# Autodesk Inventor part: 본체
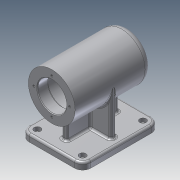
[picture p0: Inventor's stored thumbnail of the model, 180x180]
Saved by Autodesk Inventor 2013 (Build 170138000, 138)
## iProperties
Created: 2020-10
Part Number: 본체
Material: 알루미늄 6061
Document SubType Name: Modeling
Designer: CADCOM
Density: 2.71 g/cm^3
Mass: 1030.08 g
Surface Area: 757.984 cm^2
Volume: 380.103 cm^3
Author: CADCOM
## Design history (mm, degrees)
sketch "스케치1"
  geometry: C1 r 34 at (0, 0); 1 further point
  constraints: 1 centre point, 1 coincident
  dimensions: "d0" = 68 diameter of C1
extrude "돌출1" new body sketch "스케치1" distance "d1" = 112; taper "d2" = 0 deg
sketch "스케치2"
  geometry: L1 (-112, 34)-(0, 34) reference; L2 (0, 34)-(0, -34) reference; L3 (0, -34)-(-112, -34) reference; L4 (-112, -34)-(-112, 34) reference; L5 (-112, 0)-(0, 0); L6 (0, 0)-(0, 21); L7 (0, 21)-(-15, 21); L8 (-15, 21)-(-15, 24); L9 (-15, 24)-(-69, 24); L10 (-69, 24)-(-69, 21); L11 (-69, 21)-(-81, 21); L12 (-81, 21)-(-81, 17.5); L13 (-81, 17.5)-(-99, 17.5); L14 (-99, 17.5)-(-99, 16); L15 (-99, 16)-(-103, 16); L16 (-103, 16)-(-103, 10.5); L17 (-103, 10.5)-(-106, 10.5); L18 (-106, 10.5)-(-106, 0)
  constraints: 28 end point, 6 parallel, 6 perpendicular, 2 point on line, 1 collinear, 1 midpoint
  dimensions: "d3" = 15 distance of L6.end L7.end; "d5" = 54 distance of L8.end L9.end; "d6" = 12 distance of L10.end L11.end; "d7" = 18 distance of L12.end L13.end; "d8" = 4 distance of L14.end L15.end; "d9" = 3 distance of L16.end L17.end; "d10" = 42 diameter of L7 L5; "d11" = 48 diameter of L9 L5; "d12" = 42 diameter of L11 L5; "d13" = 35 diameter of L13 L5; "d14" = 32 diameter of L15 L5; "d15" = 21 diameter of L17 L5
revolve "회전1" sketch "스케치2" stored, may be unused: angle "d16" = 90 deg
node "작업 평면1"
sketch "스케치3"
  geometry: L1 (112, -34)-(112, 34) reference; L2 (0, 34)-(0, -34) reference; L3 (0, 34)-(112, 34) reference; L4 (0, -34)-(112, -34) reference; L5 (0, 0)-(112, 0); L6 (56, 34)-(56, -34); L7 (0, -45)-(112, -45); L8 (112, -45)-(112, 45); L9 (112, 45)-(0, 45); L10 (0, 45)-(0, -45); L11 (0, -45)-(112, 45); L12 (112, -45)-(0, 45); 1 further point
  constraints: 16 end point, 6 midpoint, 2 parallel, 1 horizontal, 1 perpendicular
  dimensions: "d18" = 112 distance of L8.end L9.end; "d20" = 90 distance of L7.end L8.end
extrude "돌출2" join sketch "스케치3" distance "d21" = 10; taper "d22" = 0 deg
sketch "스케치4"
  geometry: L1 (0, -45)-(112, -45) reference; L2 (112, -45)-(112, 45) reference; L3 (112, 45)-(0, 45) reference; L4 (0, 45)-(0, -45) reference; L5 (0, 0)-(112, 0); L6 (18, 4)-(94, 4); L7 (94, 4)-(94, -4); L8 (94, -4)-(18, -4); L9 (18, -4)-(18, 4); L10 (56, 45)-(56, -45); 1 further point
  constraints: 12 end point, 4 midpoint, 2 parallel, 1 horizontal, 1 horizontal alignment, 1 perpendicular
  dimensions: "d24" = 8 distance of L6.end L7.end; "d26" = 18 distance between parallel lines of L2 L7; "d27" = 18 distance between parallel lines of L4 L9
extrude "돌출3" join sketch "스케치4" stored distance "d28" = 10; taper "d29" = 0 deg
node "작업 평면2"
sketch "스케치5"
  geometry: L1 (-45, -74)-(-45, -64) reference; L2 (-45, -64)-(-4, -64) reference; L3 (-4, -64)-(-4, -33.764) reference; L4 (4, -33.764)-(4, -64) reference; L5 (4, -64)-(45, -64) reference; L6 (45, -64)-(45, -74) reference; L7 (45, -74)-(-45, -74) reference; L8 (-34, 0)-(-34, -64); L9 (34, 0)-(34, -64); C1 r 24 at (0, 0) reference; A1 r 34 centre (0, 0) between (4, -33.764) and (-4, -33.764) reference; 1 further point
  constraints: 4 end point, 2 perpendicular, 2 point on circle, 2 point on line
  dimensions: "d31" = 68 distance between parallel lines of L9 L8; "d32" = 11 distance between parallel lines of L8 L1
feature "리브1" sketch "스케치5" dims "d33" = 1, "d34" = 8, "d35" = 0, "d36" = 0, "d37" = 1, "d38" = 1
fillet "모깎기1" dims "d50" = 12
sketch "스케치7"
  geometry: C1 r 4.75 at (12, 33); C2 r 4.75 at (100, 33); C3 r 4.75 at (100, -33); C4 r 4.75 at (12, -33); A1 r 12 centre (12, 33) between (12, 45) and (0, 33) reference; A2 r 12 centre (12, -33) between (0, -33) and (12, -45) reference; A3 r 12 centre (100, -33) between (100, -45) and (112, -33) reference; A4 r 12 centre (100, 33) between (112, 33) and (100, 45) reference; 1 further point
  constraints: 4 centre point, 4 coincident
  dimensions: "d51" = 9.5 diameter of C1; "d52" = 9.5 diameter of C2; "d53" = 9.5 diameter of C3; "d54" = 9.5 diameter of C4
extrude "돌출4" cut sketch "스케치7" distance "d55" = 5.4; taper "d56" = 0 deg
sketch "스케치8"
  geometry: C1 r 2.75 at (12, 33); C2 r 2.75 at (100, 33); C3 r 2.75 at (100, -33); C4 r 2.75 at (12, -33); A1 r 12 centre (12, 33) between (12, 45) and (0, 33) reference; A2 r 12 centre (12, -33) between (0, -33) and (12, -45) reference; A3 r 12 centre (100, -33) between (100, -45) and (112, -33) reference; A4 r 12 centre (100, 33) between (112, 33) and (100, 45) reference; 1 further point
  constraints: 4 centre point, 4 coincident
  dimensions: "d57" = 5.5 diameter of C1; "d58" = 5.5 diameter of C2; "d59" = 5.5 diameter of C3; "d60" = 5.5 diameter of C4
extrude "돌출5" cut sketch "스케치8" stored distance "d61" = 5.4; taper "d62" = 0 deg
sketch "스케치9"
  geometry: L1 (88, 0)-(0, 0) reference; L2 (100, -10)-(100, 0) reference; L3 (-12, 0)-(-12, -10) reference; 2 further points
  constraints: 1 other
  dimensions: "d64" = 3 distance from line of L1 point (44, -3); "d77" = 56 distance from line of L3 point (44, -3)
feature "엠보싱1" sketch "스케치9" dims "d65" = 0.5, "d66" = 0
fillet "모깎기2" dims "d67" = 3
fillet "모깎기3" dims "d68" = 3
fillet "모깎기4" dims "d69" = 3
fillet "모깎기5" dims "d70" = 10
fillet "모깎기6" dims "d71" = 3
fillet "모깎기7" dims "d72" = 3
chamfer "모따기1" distance "d73" = 1; stored, may be unused: second distance "d74" = 2, angle "d75" = 45 deg
fillet "모깎기8" dims "d76" = 0.3
sketch "스케치10" dims "d79" = 52
  geometry: C1 r 34 at (0, 0) reference; C2 r 22 at (0, 0) reference; 2 further points
  constraints: 2 horizontal alignment, 1 coincident, 2 other
hole "구멍2" sketch "스케치10" at (26, 0) diameter "d80" = 3.242; stored, may be unused: countersink angle "d84" = 90 deg, drill point angle "d86" = 118 deg; dims "d81" = 8, "d82" = 4, "d83" = 2, "d85" = 11
node "솔리드1"
mirror "대칭1"
pattern_circular "원형 패턴2" dims angle "d88" = 360 deg
node "투영된 루프1"
node "절단 모서리 투영1"
node "절단 모서리 투영2"
other parameters: "d17" = -74, "d30" = 56
